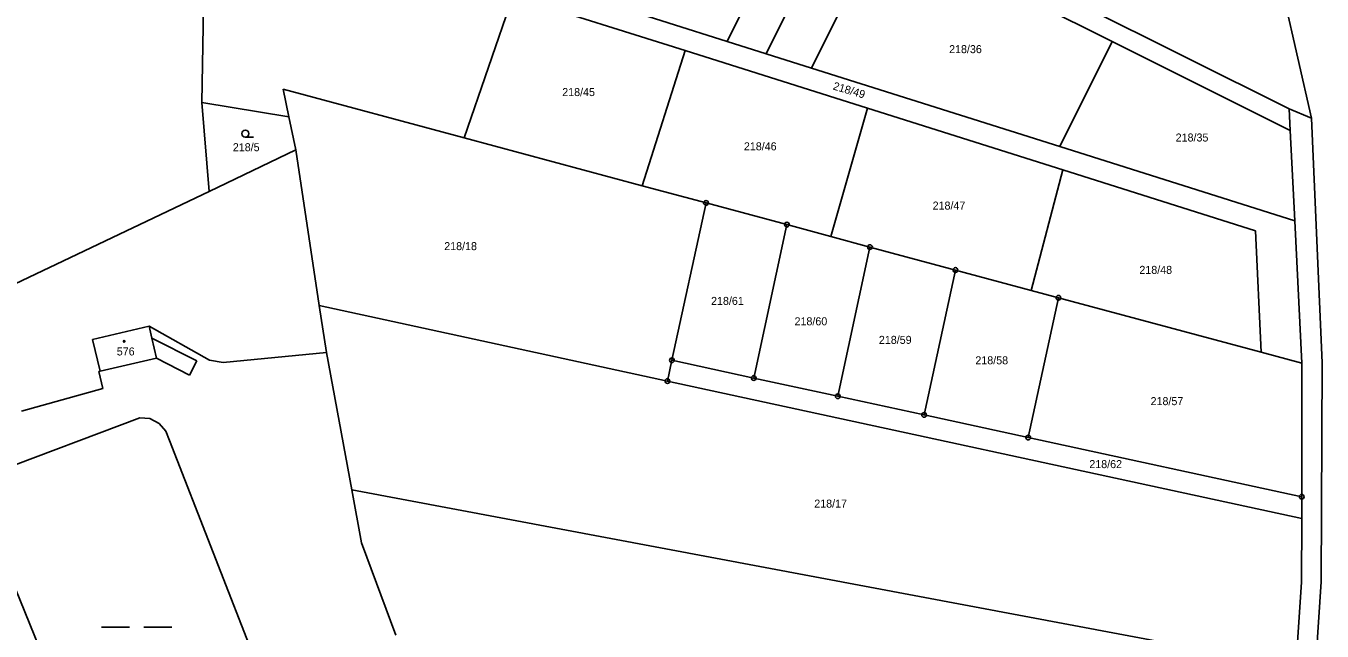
# Model space of a CAD drawing. Extents: x -735249 to -729401, y -1124843 to -1121828.
# Drawn here: x -733806.2 to -733530.8, y -1123248.5 to -1123120 of the extents above; entities that cross this region are included whole.
import ezdxf

# ---------------------------------------------------------------- set-up
doc = ezdxf.new("R2010")
doc.units = 0
for name, color, linetype in [('Vrstva 1', 7, 'Continuous'), ('Vrstva 18', 7, 'Continuous'), ('Vrstva 19', 7, 'Continuous'), ('Vrstva 25', 7, 'Continuous'), ('Vrstva 4', 7, 'Continuous')]:
    doc.layers.add(name, color=color, linetype=linetype)

msp = doc.modelspace()

# ---------------------------------------------------------------- linework, layer by layer
at = {"layer": 'Vrstva 1'}
for points in [[(-733640.87, -1123090.61), (-733657.18, -1123123.3)], [(-733537.74, -1123137.59), (-733626.29, -1123093.42)], [(-733768.12, -1123099.89), (-733768.76, -1123136.23)], [(-733624.28, -1123098.89), (-733639.27, -1123128.96)], [(-733624.28, -1123098.89), (-733575.36, -1123123.29)], [(-733541.73, -1123101.29), (-733533.03, -1123139.56)], [(-733713.01, -1123143.76), (-733702.72, -1123113.66)], [(-733702.72, -1123113.66), (-733666.09, -1123125.22)], [(-733648.85, -1123125.93), (-733642.55, -1123113.22)], [(-733657.18, -1123123.3), (-733682.21, -1123115.4)], [(-733666.09, -1123125.22), (-733675.2, -1123153.93)], [(-733666.09, -1123125.22), (-733627.34, -1123137.45)], [(-733657.18, -1123123.3), (-733648.85, -1123125.93)], [(-733586.5, -1123145.62), (-733575.36, -1123123.29)], [(-733575.36, -1123123.29), (-733537.51, -1123142.18)], [(-733639.27, -1123128.96), (-733648.85, -1123125.93)], [(-733586.5, -1123145.62), (-733639.27, -1123128.96)], [(-733713.01, -1123143.76), (-733751.49, -1123133.4)], [(-733750.27, -1123139.28), (-733751.49, -1123133.4)], [(-733768.76, -1123136.23), (-733767.24, -1123155.12)], [(-733768.76, -1123136.23), (-733750.27, -1123139.28)], [(-733750.27, -1123139.28), (-733748.81, -1123146.34)], [(-733627.34, -1123137.45), (-733635.1, -1123164.71)], [(-733627.34, -1123137.45), (-733585.83, -1123150.55)], [(-733533.03, -1123139.56), (-733537.74, -1123137.59)], [(-733537.74, -1123137.59), (-733537.51, -1123142.18)], [(-733537.51, -1123142.18), (-733536.54, -1123161.39)], [(-733533.03, -1123139.56), (-733530.75, -1123191.52)], [(-733675.2, -1123153.93), (-733713.01, -1123143.76)], [(-733767.24, -1123155.12), (-733748.81, -1123146.34)], [(-733748.81, -1123146.34), (-733743.82, -1123179.37)], [(-733536.54, -1123161.39), (-733586.5, -1123145.62)], [(-733585.83, -1123150.55), (-733592.54, -1123176.15)], [(-733585.83, -1123150.55), (-733544.89, -1123163.47)], [(-733817.42, -1123179.03), (-733767.24, -1123155.12)], [(-733661.65, -1123157.57), (-733675.2, -1123153.93)], [(-733661.65, -1123157.57), (-733668.89, -1123190.99)], [(-733644.46, -1123162.19), (-733661.65, -1123157.57)], [(-733535.02, -1123191.62), (-733536.54, -1123161.39)], [(-733644.46, -1123162.19), (-733651.52, -1123194.75)], [(-733635.1, -1123164.71), (-733644.46, -1123162.19)], [(-733544.89, -1123163.47), (-733543.72, -1123189.28)], [(-733626.81, -1123166.94), (-733635.1, -1123164.71)], [(-733626.81, -1123166.94), (-733633.67, -1123198.61)], [(-733608.65, -1123171.82), (-733626.81, -1123166.94)], [(-733608.65, -1123171.82), (-733615.31, -1123202.59)], [(-733592.54, -1123176.15), (-733608.65, -1123171.82)], [(-733586.76, -1123177.71), (-733593.18, -1123207.38)], [(-733586.76, -1123177.71), (-733592.54, -1123176.15)], [(-733543.72, -1123189.28), (-733586.76, -1123177.71)], [(-733743.82, -1123179.37), (-733742.31, -1123189.35)], [(-733669.84, -1123195.39), (-733743.82, -1123179.37)], [(-733767.18, -1123190.97), (-733779.98, -1123183.75)], [(-733779.98, -1123183.75), (-733779.38, -1123186.27)], [(-733779.38, -1123186.27), (-733769.83, -1123191.13)], [(-733778.39, -1123190.5), (-733790.39, -1123193.32)], [(-733771.38, -1123194.12), (-733778.39, -1123190.5)], [(-733769.83, -1123191.13), (-733771.38, -1123194.12)], [(-733764.27, -1123191.47), (-733767.18, -1123190.97)], [(-733764.27, -1123191.47), (-733742.31, -1123189.35)], [(-733742.31, -1123189.35), (-733736.92, -1123218.48)], [(-733668.89, -1123190.99), (-733669.84, -1123195.39)], [(-733668.89, -1123190.99), (-733651.52, -1123194.75)], [(-733535.02, -1123191.62), (-733543.72, -1123189.28)], [(-733535.07, -1123219.96), (-733535.02, -1123191.62)], [(-733530.92, -1123238.05), (-733530.75, -1123191.52)], [(-733790.39, -1123193.32), (-733790.65, -1123193.34)], [(-733790.65, -1123193.34), (-733789.81, -1123196.99)], [(-733789.81, -1123196.99), (-733807.08, -1123201.8)], [(-733535.08, -1123224.56), (-733669.84, -1123195.39)], [(-733651.52, -1123194.75), (-733633.67, -1123198.61)], [(-733633.67, -1123198.61), (-733615.31, -1123202.59)], [(-733615.31, -1123202.59), (-733593.18, -1123207.38)], [(-733593.18, -1123207.38), (-733535.07, -1123219.96)], [(-733736.92, -1123218.48), (-733734.83, -1123229.77)], [(-733736.92, -1123218.48), (-733540.13, -1123255.42)], [(-733535.08, -1123224.56), (-733535.07, -1123219.96)], [(-733535.11, -1123238.11), (-733535.08, -1123224.56)], [(-733734.83, -1123229.77), (-733727.57, -1123249.33)], [(-733536.3, -1123256.14), (-733535.11, -1123238.11)], [(-733534.07, -1123285.18), (-733530.92, -1123238.05)]]:
    msp.add_lwpolyline(points, dxfattribs=at)
at = {"layer": 'Vrstva 25'}
for points in [[(-733759.53, -1123143.62), (-733757.78, -1123143.62)], [(-733790.13, -1123247.61), (-733784.13, -1123247.61)], [(-733781.13, -1123247.61), (-733775.13, -1123247.61)]]:
    msp.add_lwpolyline(points, dxfattribs=at)
for centre, radius in [((-733759.53, -1123142.87), 0.75), ((-733661.65, -1123157.57), 0.5), ((-733661.65, -1123157.57), 0.032), ((-733644.46, -1123162.19), 0.5), ((-733644.46, -1123162.19), 0.032), ((-733626.81, -1123166.94), 0.5), ((-733626.81, -1123166.94), 0.032), ((-733608.65, -1123171.82), 0.5), ((-733608.65, -1123171.82), 0.032), ((-733586.76, -1123177.71), 0.5), ((-733586.76, -1123177.71), 0.032), ((-733785.28, -1123186.97), 0.175), ((-733668.89, -1123190.99), 0.5), ((-733668.89, -1123190.99), 0.032), ((-733651.52, -1123194.75), 0.5), ((-733669.84, -1123195.39), 0.5), ((-733669.84, -1123195.39), 0.032), ((-733651.52, -1123194.75), 0.032), ((-733633.67, -1123198.61), 0.5), ((-733633.67, -1123198.61), 0.032), ((-733615.31, -1123202.59), 0.5), ((-733615.31, -1123202.59), 0.032), ((-733593.18, -1123207.38), 0.5), ((-733593.18, -1123207.38), 0.032), ((-733535.07, -1123219.96), 0.5), ((-733535.07, -1123219.96), 0.032)]:
    msp.add_circle(centre, radius, dxfattribs=at)
at = {"layer": 'Vrstva 4'}
for points in [[(-733792, -1123186.57), (-733779.98, -1123183.75)], [(-733779.38, -1123186.27), (-733778.39, -1123190.5)], [(-733790.39, -1123193.32), (-733792, -1123186.57)], [(-733781.93, -1123203.21), (-733812.84, -1123214.84)], [(-733779.86, -1123203.34), (-733781.93, -1123203.21)], [(-733777.81, -1123204.41), (-733779.86, -1123203.34)], [(-733776.43, -1123206.06), (-733777.81, -1123204.41)], [(-733775.63, -1123208.01), (-733776.43, -1123206.06)], [(-733775.63, -1123208.01), (-733747.84, -1123279.38)], [(-733815.44, -1123222.27), (-733786.3, -1123293.91)]]:
    msp.add_lwpolyline(points, dxfattribs=at)

# ---------------------------------------------------------------- texts
at = {"layer": 'Vrstva 18'}
for s, p in [('218/36', (-733610, -1123125.78)), ('218/45', (-733692.2, -1123134.89)), ('218/5', (-733762.19, -1123146.6)), ('218/46', (-733653.6, -1123146.41)), ('218/35', (-733561.86, -1123144.54)), ('218/47', (-733613.5, -1123158.99)), ('218/18', (-733717.27, -1123167.6)), ('218/48', (-733569.57, -1123172.64)), ('218/61', (-733660.578, -1123179.23)), ('218/60', (-733642.838, -1123183.56)), ('218/59', (-733624.918, -1123187.5)), ('218/58', (-733604.418, -1123191.84)), ('218/57', (-733567.188, -1123200.51)), ('218/62', (-733580.208, -1123213.88)), ('218/17', (-733638.65, -1123222.26))]:
    msp.add_text(s, height=1.7, dxfattribs=at).set_placement(p)
msp.add_text('218/49', height=1.7, rotation=343.50273, dxfattribs=at).set_placement((-733634.802, -1123133.466))
at = {"layer": 'Vrstva 19'}
msp.add_text('576', height=1.7, dxfattribs=at).set_placement((-733786.85, -1123189.96))

doc.saveas('drawing.dxf')
